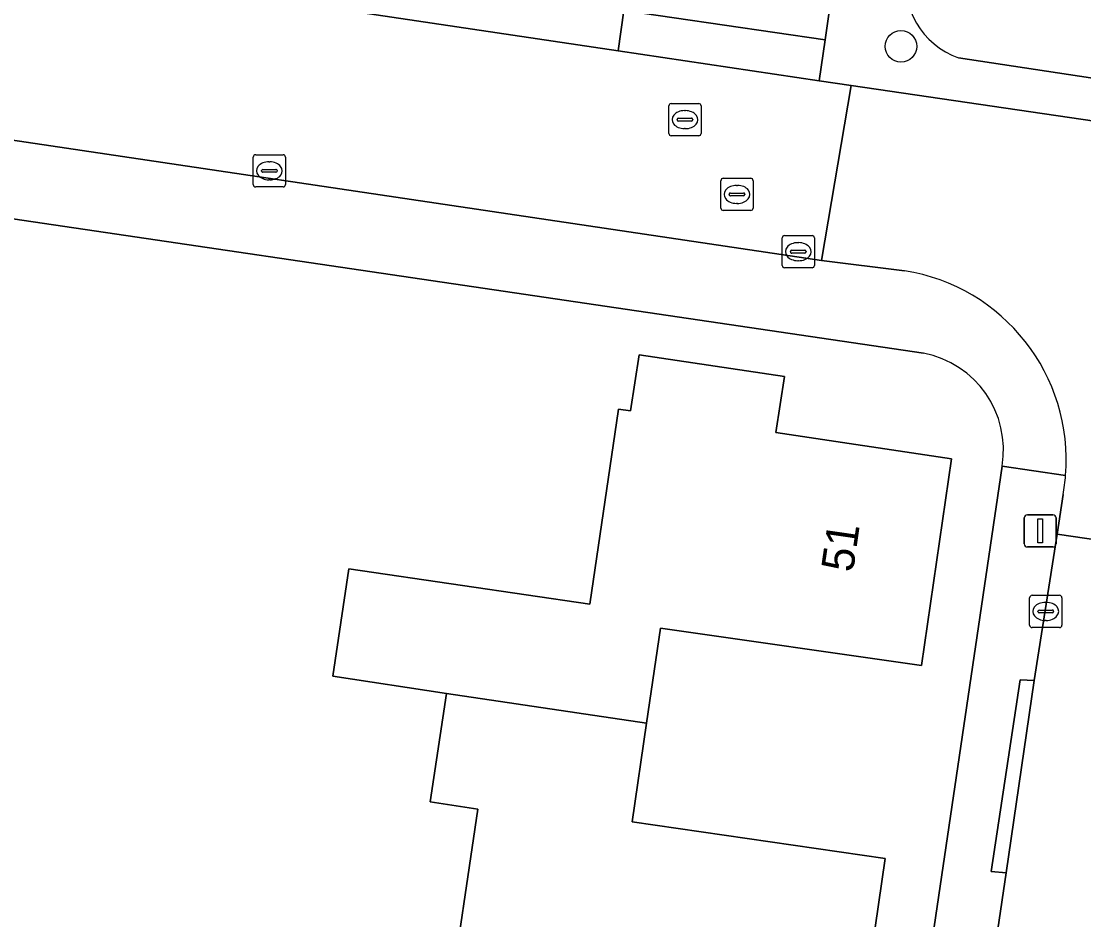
# Model space of a CAD drawing. Extents: x 164148 to 165261, y 382513 to 383432.
# Drawn here: x 164438.16 to 164471.14, y 383173.31 to 383201.2 of the extents above; entities that cross this region are included whole.
import ezdxf

# ---------------------------------------------------------------- set-up
doc = ezdxf.new("R2010")
doc.units = 0
for name, color, linetype in [('IMGEO_Boom', 7, 'Continuous'), ('IMGEO_Erf', 7, 'Continuous'), ('IMGEO_Greppel_droge_sloot', 7, 'Continuous'), ('IMGEO_Groenvoorziening', 7, 'Continuous'), ('IMGEO_Kolk', 7, 'Continuous'), ('IMGEO_Lichtmast', 7, 'Continuous'), ('IMGEO_Pand', 7, 'Continuous'), ('IMGEO_Pand_nummerreeks', 7, 'Continuous'), ('IMGEO_Rijbaan_lokaal_open', 7, 'Continuous'), ('IMGEO_Rioolput', 7, 'Continuous'), ('IMGEO_Voetpad_open', 7, 'Continuous')]:
    doc.layers.add(name, color=color, linetype=linetype)

msp = doc.modelspace()

# ---------------------------------------------------------------- linework, layer by layer
at = {"layer": 'IMGEO_Boom'}
msp.add_circle((164465.465, 383200.418), 0.489, dxfattribs=at)
at = {"layer": 'IMGEO_Erf'}
for points in [[(164466.162, 383190.893), (164425.199, 383196.935)], [(164451.41, 383170.512), (164452.339, 383176.742), (164450.856, 383176.963), (164451.357, 383180.331), (164447.838, 383180.872), (164448.331, 383184.203), (164451.856, 383183.682), (164455.805, 383183.103), (164456.7, 383189.158), (164457.076, 383189.102), (164457.336, 383190.843), (164461.849, 383190.169), (164461.579, 383188.432), (164467.036, 383187.619), (164466.104, 383181.203), (164458.001, 383182.356), (164457.573, 383179.411), (164457.129, 383176.349), (164464.977, 383175.21), (164464.054, 383168.85)], [(164452.978, 383081.464), (164468.608, 383187.386)]]:
    msp.add_lwpolyline(points, dxfattribs=at)
msp.add_arc((164465.588, 383187.886), 3.061, 350.5963, 79.1924, dxfattribs=at)
at = {"layer": 'IMGEO_Greppel_droge_sloot'}
msp.add_lwpolyline([(164467.251, 383200.06), (164485.079, 383197.365)], dxfattribs=at)
msp.add_arc((164468.073, 383202.38), 2.461, 89.2284, 250.4932, dxfattribs=at)
at = {"layer": 'IMGEO_Groenvoorziening'}
for points in [[(164457.598, 383206.707), (164395.381, 383215.859), (164394.664, 383210.692), (164394.494, 383209.464), (164408.334, 383207.467), (164430.112, 383204.244), (164456.689, 383200.283), (164456.866, 383201.529)], [(164491.129, 383201.718), (164463.85, 383205.804), (164463.111, 383200.617), (164462.931, 383199.353), (164463.916, 383199.206), (164485.446, 383196.052), (164490.177, 383195.349), (164490.359, 383196.569)]]:
    msp.add_lwpolyline(points, close=True, dxfattribs=at)
msp.add_lwpolyline([(164485.079, 383197.365), (164467.251, 383200.06)], dxfattribs=at)
msp.add_arc((164468.073, 383202.38), 2.461, 89.2284, 250.4932, dxfattribs=at)
at = {"layer": 'IMGEO_Kolk'}
for p, q in [((164445.439, 383197.055), (164446.291, 383197.055)), ((164445.364, 383196.129), (164445.364, 383196.981)), ((164445.852, 383196.835), (164445.877, 383196.835)), ((164446.365, 383196.981), (164446.365, 383196.129)), ((164445.623, 383196.549), (164445.623, 383196.561)), ((164446.061, 383196.512), (164445.663, 383196.512)), ((164445.666, 383196.598), (164446.064, 383196.598)), ((164446.107, 383196.561), (164446.107, 383196.549)), ((164446.291, 383196.055), (164445.439, 383196.055)), ((164445.875, 383196.275), (164445.85, 383196.275)), ((164461.779, 383193.619), (164461.779, 383194.471)), ((164461.854, 383194.545), (164462.706, 383194.545)), ((164462.78, 383194.471), (164462.78, 383193.619)), ((164462.081, 383194.088), (164462.479, 383194.088)), ((164462.267, 383194.325), (164462.292, 383194.325)), ((164462.038, 383194.039), (164462.038, 383194.051)), ((164462.476, 383194.002), (164462.078, 383194.002)), ((164462.29, 383193.765), (164462.265, 383193.765)), ((164462.522, 383194.051), (164462.522, 383194.039)), ((164462.706, 383193.545), (164461.854, 383193.545)), ((164469.46, 383182.451), (164469.46, 383183.303)), ((164469.535, 383183.377), (164470.387, 383183.377)), ((164470.461, 383183.303), (164470.461, 383182.451)), ((164469.719, 383182.871), (164469.719, 383182.883)), ((164469.762, 383182.92), (164470.16, 383182.92)), ((164469.948, 383183.157), (164469.973, 383183.157)), ((164470.203, 383182.883), (164470.203, 383182.871)), ((164470.157, 383182.834), (164469.759, 383182.834)), ((164469.971, 383182.597), (164469.946, 383182.597)), ((164470.387, 383182.377), (164469.535, 383182.377))]:
    msp.add_line(p, q, dxfattribs=at)
for points in [[(164445.439, 383197.055), (164446.291, 383197.055)], [(164445.364, 383196.129), (164445.364, 383196.981)], [(164446.365, 383196.981), (164446.365, 383196.129)], [(164446.291, 383196.055), (164445.439, 383196.055)], [(164461.779, 383193.619), (164461.779, 383194.471)], [(164461.854, 383194.545), (164462.706, 383194.545)], [(164462.78, 383194.471), (164462.78, 383193.619)], [(164462.706, 383193.545), (164461.854, 383193.545)], [(164469.46, 383182.451), (164469.46, 383183.303)], [(164469.535, 383183.377), (164470.387, 383183.377)], [(164470.461, 383183.303), (164470.461, 383182.451)], [(164470.387, 383182.377), (164469.535, 383182.377)]]:
    msp.add_lwpolyline(points, dxfattribs=at)
for centre, radius, start, end in [((164445.441, 383196.979), 0.0765, 91.552, 178.448), ((164445.441, 383196.979), 0.0765, 91.552, 178.448), ((164446.289, 383196.979), 0.0765, 1.552, 88.448), ((164446.289, 383196.979), 0.0765, 1.552, 88.448), ((164445.663, 383196.558), 0.0403, 85.8775, 175.7526), ((164445.66, 383196.548), 0.0366, 178.938, 274.7102), ((164446.064, 383196.555), 0.043, 264.8664, 352.4533), ((164446.068, 383196.56), 0.0386, 1.7309, 96.639), ((164445.441, 383196.131), 0.0765, 181.552, 268.448), ((164445.441, 383196.131), 0.0765, 181.552, 268.448), ((164446.289, 383196.131), 0.0765, 271.552, 358.448), ((164446.289, 383196.131), 0.0765, 271.552, 358.448), ((164461.856, 383194.469), 0.0765, 91.552, 178.448), ((164461.856, 383194.469), 0.0765, 91.552, 178.448), ((164462.704, 383194.469), 0.0765, 1.552, 88.448), ((164462.704, 383194.469), 0.0765, 1.552, 88.448), ((164462.078, 383194.048), 0.0403, 85.8775, 175.7526), ((164462.483, 383194.05), 0.0386, 1.7309, 96.639), ((164462.075, 383194.038), 0.0366, 178.938, 274.7102), ((164462.479, 383194.045), 0.043, 264.8664, 352.4533), ((164461.856, 383193.621), 0.0765, 181.552, 268.448), ((164461.856, 383193.621), 0.0765, 181.552, 268.448), ((164462.704, 383193.621), 0.0765, 271.552, 358.448), ((164462.704, 383193.621), 0.0765, 271.552, 358.448), ((164469.537, 383183.301), 0.0765, 91.552, 178.448), ((164469.537, 383183.301), 0.0765, 91.552, 178.448), ((164470.385, 383183.301), 0.0765, 1.552, 88.448), ((164470.385, 383183.301), 0.0765, 1.552, 88.448), ((164469.759, 383182.88), 0.0403, 85.8775, 175.7526), ((164469.756, 383182.87), 0.0366, 178.938, 274.7102), ((164470.16, 383182.877), 0.043, 264.8664, 352.4533), ((164470.164, 383182.882), 0.0386, 1.7309, 96.639), ((164469.537, 383182.453), 0.0765, 181.552, 268.448), ((164469.537, 383182.453), 0.0765, 181.552, 268.448), ((164470.385, 383182.453), 0.0765, 271.552, 358.448), ((164470.385, 383182.453), 0.0765, 271.552, 358.448)]:
    msp.add_arc(centre, radius, start, end, dxfattribs=at)
for centre, major_axis, ratio, start_param, end_param in [((164445.851, 383196.555), (-0.387, 0.002), 0.722429, 4.712389, 7.853982), ((164445.876, 383196.555), (-0.39, 0.002), 0.717154, 1.570796, 4.712389), ((164462.266, 383194.045), (-0.387, 0.002), 0.722429, 4.712389, 7.853982), ((164462.291, 383194.045), (-0.39, 0.002), 0.717154, 1.570796, 4.712389), ((164469.947, 383182.877), (-0.387, 0.002), 0.722429, 4.712389, 7.853982), ((164469.972, 383182.877), (-0.39, 0.002), 0.717154, 1.570796, 4.712389)]:
    msp.add_ellipse(centre, major_axis=major_axis, ratio=ratio, start_param=start_param, end_param=end_param, dxfattribs=at)
at = {"layer": 'IMGEO_Lichtmast'}
for p, q in [((164469.393, 383185.878), (164470.183, 383185.878)), ((164470.183, 383185.878), (164469.393, 383185.878)), ((164469.293, 383184.978), (164469.293, 383185.778)), ((164469.293, 383185.778), (164469.293, 383184.978)), ((164470.283, 383185.778), (164470.283, 383184.978)), ((164470.283, 383184.978), (164470.283, 383185.778)), ((164470.183, 383184.878), (164469.393, 383184.878)), ((164469.393, 383184.878), (164470.183, 383184.878))]:
    msp.add_line(p, q, dxfattribs=at)
msp.add_lwpolyline([(164469.713, 383185.753), (164469.863, 383185.753), (164469.863, 383185.003), (164469.713, 383185.003), (164469.713, 383185.753)], dxfattribs=at)
for centre, start, end in [((164469.393, 383185.778), 90, 180), ((164469.393, 383185.778), 90, 180), ((164470.183, 383185.778), 0, 90), ((164470.183, 383185.778), 360, 90), ((164469.393, 383184.978), 180, 270), ((164469.393, 383184.978), 180, 270), ((164470.183, 383184.978), 270, 0), ((164470.183, 383184.978), 270, 0)]:
    msp.add_arc(centre, 0.1, start, end, dxfattribs=at)
at = {"layer": 'IMGEO_Pand'}
for points in [[(164457.573, 383179.411), (164458.001, 383182.356), (164466.104, 383181.203), (164467.036, 383187.619), (164461.579, 383188.432), (164461.849, 383190.169), (164457.336, 383190.843), (164457.076, 383189.102), (164456.7, 383189.158), (164455.805, 383183.103), (164451.856, 383183.682), (164448.331, 383184.203), (164447.838, 383180.872), (164451.357, 383180.331)], [(164451.41, 383170.512), (164464.221, 383168.616), (164464.251, 383168.824), (164464.054, 383168.85), (164464.977, 383175.21), (164457.129, 383176.349), (164457.573, 383179.411), (164451.357, 383180.331), (164450.856, 383176.963), (164452.339, 383176.742)]]:
    msp.add_lwpolyline(points, close=True, dxfattribs=at)
at = {"layer": 'IMGEO_Rijbaan_lokaal_open'}
msp.add_lwpolyline([(164462.931, 383199.353), (164456.689, 383200.283), (164430.112, 383204.244), (164429.333, 383198.784), (164463.004, 383193.776), (164463.916, 383199.206)], close=True, dxfattribs=at)
for points in [[(164463.916, 383199.206), (164463.004, 383193.776)], [(164485.446, 383196.052), (164463.916, 383199.206)], [(164463.004, 383193.776), (164465.575, 383193.453)], [(164470.497, 383186.507), (164470.315, 383185.277)], [(164459.638, 383078.969), (164459.743, 383079.423), (164474.705, 383181.346), (164475.197, 383184.563), (164470.315, 383185.277), (164469.603, 383180.729), (164468.729, 383174.758), (164466.829, 383161.888), (164465.928, 383155.914), (164464.06, 383143.063), (164463.157, 383137.09), (164461.828, 383127.818), (164461.355, 383124.821), (164459.467, 383111.861), (164458.569, 383105.925), (164456.676, 383093.112), (164455.779, 383087.125), (164455.078, 383082.177)], [(164470.315, 383185.277), (164475.197, 383184.563)]]:
    msp.add_lwpolyline(points, dxfattribs=at)
for centre, radius, start, end in [((164464.649, 383187.58), 5.946, 355.3333, 81.0393), ((164464.295, 383187.628), 6.303, 349.7547, 355.158)]:
    msp.add_arc(centre, radius, start, end, dxfattribs=at)
at = {"layer": 'IMGEO_Rioolput'}
for p, q in [((164458.262, 383197.718), (164458.262, 383198.57)), ((164458.337, 383198.644), (164459.189, 383198.644)), ((164458.75, 383198.424), (164458.775, 383198.424)), ((164459.263, 383198.57), (164459.263, 383197.718)), ((164458.521, 383198.138), (164458.521, 383198.15)), ((164458.959, 383198.101), (164458.561, 383198.101)), ((164458.564, 383198.187), (164458.962, 383198.187)), ((164459.005, 383198.15), (164459.005, 383198.138)), ((164458.773, 383197.864), (164458.748, 383197.864)), ((164459.189, 383197.644), (164458.337, 383197.644)), ((164459.877, 383195.397), (164459.877, 383196.249)), ((164459.952, 383196.323), (164460.804, 383196.323)), ((164460.365, 383196.103), (164460.39, 383196.103)), ((164460.878, 383196.249), (164460.878, 383195.397)), ((164460.136, 383195.817), (164460.136, 383195.829)), ((164460.574, 383195.78), (164460.176, 383195.78)), ((164460.179, 383195.866), (164460.577, 383195.866)), ((164460.62, 383195.829), (164460.62, 383195.817)), ((164460.388, 383195.543), (164460.363, 383195.543)), ((164460.804, 383195.323), (164459.952, 383195.323))]:
    msp.add_line(p, q, dxfattribs=at)
for points in [[(164458.262, 383197.718), (164458.262, 383198.57)], [(164458.337, 383198.644), (164459.189, 383198.644)], [(164459.263, 383198.57), (164459.263, 383197.718)], [(164459.189, 383197.644), (164458.337, 383197.644)], [(164459.877, 383195.397), (164459.877, 383196.249)], [(164459.952, 383196.323), (164460.804, 383196.323)], [(164460.878, 383196.249), (164460.878, 383195.397)], [(164460.804, 383195.323), (164459.952, 383195.323)]]:
    msp.add_lwpolyline(points, dxfattribs=at)
for centre, radius, start, end in [((164458.339, 383198.568), 0.0765, 91.552, 178.448), ((164458.339, 383198.568), 0.0765, 91.552, 178.448), ((164459.187, 383198.568), 0.0765, 1.552, 88.448), ((164459.187, 383198.568), 0.0765, 1.552, 88.448), ((164458.561, 383198.147), 0.0403, 85.8775, 175.7526), ((164458.558, 383198.137), 0.0366, 178.938, 274.7102), ((164458.962, 383198.144), 0.043, 264.8664, 352.4533), ((164458.966, 383198.149), 0.0386, 1.7309, 96.639), ((164458.339, 383197.72), 0.0765, 181.552, 268.448), ((164458.339, 383197.72), 0.0765, 181.552, 268.448), ((164459.187, 383197.72), 0.0765, 271.552, 358.448), ((164459.187, 383197.72), 0.0765, 271.552, 358.448), ((164459.954, 383196.247), 0.0765, 91.552, 178.448), ((164459.954, 383196.247), 0.0765, 91.552, 178.448), ((164460.802, 383196.247), 0.0765, 1.552, 88.448), ((164460.802, 383196.247), 0.0765, 1.552, 88.448), ((164460.176, 383195.826), 0.0403, 85.8775, 175.7526), ((164460.173, 383195.816), 0.0366, 178.938, 274.7102), ((164460.577, 383195.823), 0.043, 264.8664, 352.4533), ((164460.581, 383195.828), 0.0386, 1.7309, 96.639), ((164459.954, 383195.399), 0.0765, 181.552, 268.448), ((164459.954, 383195.399), 0.0765, 181.552, 268.448), ((164460.802, 383195.399), 0.0765, 271.552, 358.448), ((164460.802, 383195.399), 0.0765, 271.552, 358.448)]:
    msp.add_arc(centre, radius, start, end, dxfattribs=at)
for centre, major_axis, ratio, start_param, end_param in [((164458.749, 383198.144), (-0.387, 0.002), 0.722429, 4.712389, 7.853982), ((164458.774, 383198.144), (-0.39, 0.002), 0.717154, 1.570796, 4.712389), ((164460.364, 383195.823), (-0.387, 0.002), 0.722429, 4.712389, 7.853982), ((164460.389, 383195.823), (-0.39, 0.002), 0.717154, 1.570796, 4.712389)]:
    msp.add_ellipse(centre, major_axis=major_axis, ratio=ratio, start_param=start_param, end_param=end_param, dxfattribs=at)
at = {"layer": 'IMGEO_Voetpad_open'}
for points in [[(164463.85, 383205.804), (164463.935, 383206.398), (164464.719, 383208.19), (164457.605, 383209.179), (164457.683, 383207.301), (164457.598, 383206.707), (164456.866, 383201.529), (164463.111, 383200.617)], [(164462.931, 383199.353), (164463.111, 383200.617), (164456.866, 383201.529), (164456.689, 383200.283)], [(164469.603, 383180.729), (164469.163, 383180.755), (164468.264, 383174.806), (164468.729, 383174.758)]]:
    msp.add_lwpolyline(points, close=True, dxfattribs=at)
for points in [[(164465.575, 383193.453), (164463.004, 383193.776), (164429.333, 383198.784)], [(164425.199, 383196.935), (164466.162, 383190.893)], [(164470.575, 383187.096), (164468.608, 383187.386), (164452.978, 383081.464)], [(164468.608, 383187.386), (164470.575, 383187.096)], [(164459.467, 383111.861), (164461.355, 383124.821), (164460.906, 383124.891), (164461.372, 383127.859), (164461.828, 383127.818), (164463.157, 383137.09), (164462.704, 383137.16), (164463.598, 383143.151), (164464.06, 383143.063), (164465.928, 383155.914), (164465.483, 383156.011), (164466.399, 383161.964), (164466.829, 383161.888), (164468.729, 383174.758), (164468.264, 383174.806), (164469.163, 383180.755), (164469.603, 383180.729), (164470.315, 383185.277), (164470.497, 383186.507)]]:
    msp.add_lwpolyline(points, dxfattribs=at)
for centre, radius, start, end in [((164464.649, 383187.58), 5.946, 355.3333, 81.0393), ((164465.588, 383187.886), 3.061, 350.5963, 79.1924), ((164464.295, 383187.628), 6.303, 349.7547, 355.158)]:
    msp.add_arc(centre, radius, start, end, dxfattribs=at)

# ---------------------------------------------------------------- texts
at = {"layer": 'IMGEO_Pand_nummerreeks'}
msp.add_text('51', height=1, rotation=81.7345, dxfattribs=at).set_placement((164463.974, 383184.067))

doc.saveas('drawing.dxf')
